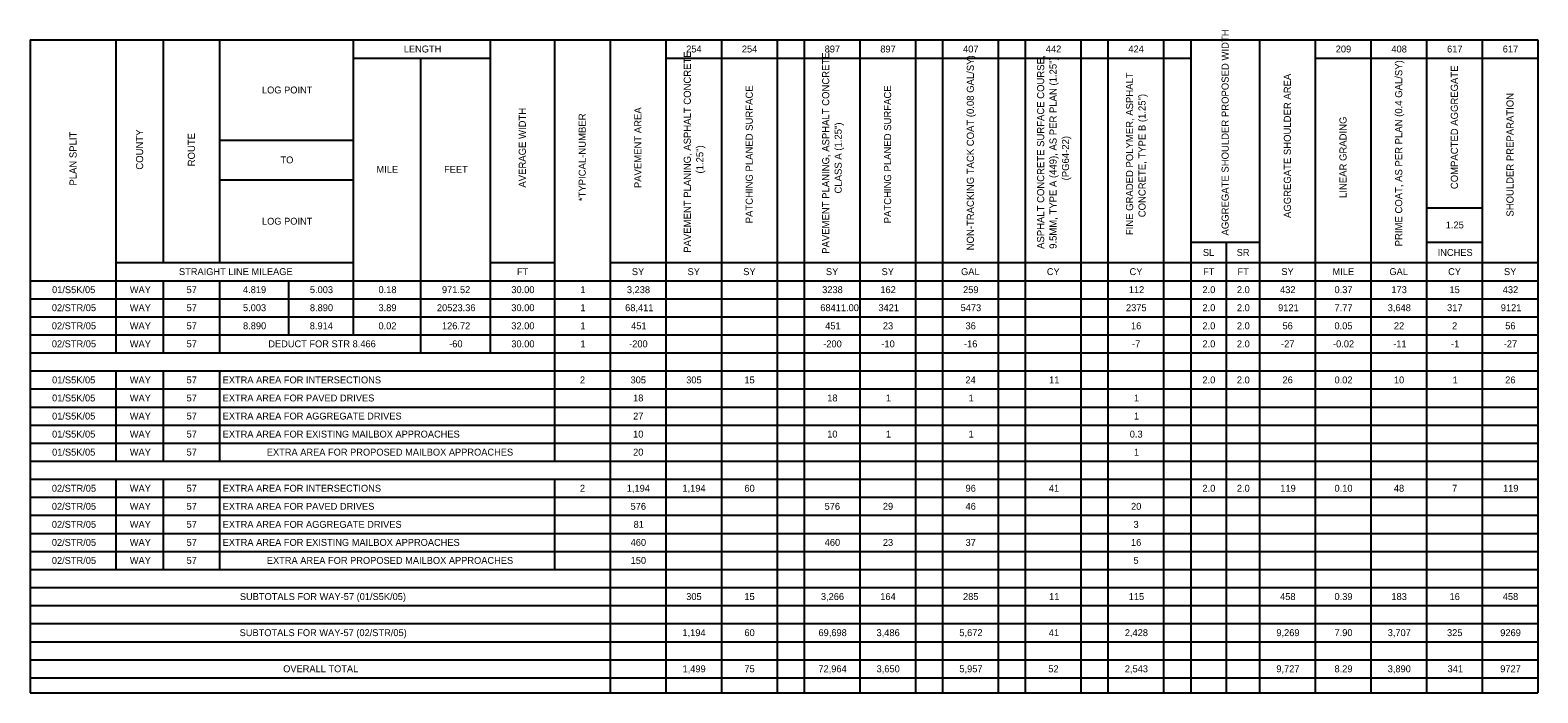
# Model space of a CAD drawing. Extents: x 12069 to 12219, y 28137 to 28231.
# Drawn here: x 12069.45 to 12099.95, y 28161.27 to 28174.68 of the extents above; entities that cross this region are included whole.
import ezdxf

# ---------------------------------------------------------------- set-up
doc = ezdxf.new("R2010")
doc.units = 0
doc.layers.add('SH_Data', color=7, linetype='Continuous')

msp = doc.modelspace()

# ---------------------------------------------------------------- linework, layer by layer
at = {"layer": 'SH_Data'}
for p, q in [((12069.445, 28174.479), (12099.945, 28174.479)), ((12069.445, 28174.479), (12069.445, 28168.149)), ((12071.182, 28174.479), (12071.182, 28168.149)), ((12072.136, 28174.479), (12072.136, 28169.975)), ((12073.277, 28174.479), (12073.277, 28169.975)), ((12075.983, 28174.479), (12075.983, 28168.514)), ((12078.752, 28174.479), (12078.752, 28168.149)), ((12080.05, 28174.479), (12080.05, 28165.957)), ((12081.176, 28174.479), (12081.176, 28161.27)), ((12082.302, 28174.479), (12082.302, 28161.27)), ((12083.428, 28174.479), (12083.428, 28161.27)), ((12084.555, 28174.479), (12084.555, 28161.27)), ((12085.102, 28174.479), (12085.102, 28161.27)), ((12086.228, 28174.479), (12086.228, 28161.27)), ((12087.354, 28174.479), (12087.354, 28161.27)), ((12087.902, 28174.479), (12087.902, 28161.27)), ((12089.028, 28174.479), (12089.028, 28161.27)), ((12089.575, 28174.479), (12089.575, 28161.27)), ((12090.702, 28174.479), (12090.702, 28161.27)), ((12091.249, 28174.479), (12091.249, 28161.27)), ((12092.375, 28174.479), (12092.375, 28161.27)), ((12092.923, 28174.479), (12092.923, 28161.27)), ((12094.315, 28174.479), (12094.315, 28161.27)), ((12095.441, 28174.479), (12095.441, 28161.27)), ((12096.567, 28174.479), (12096.567, 28161.27)), ((12097.693, 28174.479), (12097.693, 28161.27)), ((12098.819, 28174.479), (12098.819, 28161.27)), ((12099.945, 28174.479), (12099.945, 28161.575)), ((12075.983, 28174.114), (12078.752, 28174.114)), ((12077.344, 28174.114), (12077.344, 28168.149)), ((12082.302, 28174.114), (12092.923, 28174.114)), ((12095.441, 28174.114), (12099.945, 28174.114)), ((12073.277, 28172.455), (12075.983, 28172.455)), ((12073.277, 28171.649), (12075.983, 28171.649)), ((12097.693, 28171.086), (12098.819, 28171.086)), ((12092.923, 28170.386), (12094.315, 28170.386)), ((12093.642, 28170.386), (12093.642, 28161.27)), ((12097.693, 28170.386), (12098.819, 28170.386)), ((12071.182, 28169.975), (12075.983, 28169.975)), ((12078.752, 28169.975), (12080.05, 28169.975)), ((12081.176, 28169.975), (12099.945, 28169.975)), ((12069.445, 28169.609), (12099.945, 28169.609)), ((12072.136, 28169.609), (12072.136, 28168.149)), ((12073.277, 28169.609), (12073.277, 28168.149)), ((12074.67, 28169.609), (12074.67, 28168.514)), ((12069.445, 28169.244), (12099.945, 28169.244)), ((12069.445, 28168.879), (12099.945, 28168.879)), ((12069.445, 28168.514), (12099.945, 28168.514)), ((12069.445, 28168.149), (12099.945, 28168.149)), ((12069.445, 28168.149), (12069.445, 28167.783)), ((12069.445, 28167.783), (12099.945, 28167.783)), ((12069.445, 28167.783), (12069.445, 28165.957)), ((12071.182, 28167.783), (12071.182, 28165.957)), ((12072.136, 28167.783), (12072.136, 28165.957)), ((12073.277, 28167.783), (12073.277, 28165.957)), ((12069.445, 28167.418), (12099.945, 28167.418)), ((12069.445, 28167.053), (12099.945, 28167.053)), ((12069.445, 28166.688), (12099.945, 28166.688)), ((12069.445, 28166.323), (12099.945, 28166.323)), ((12069.445, 28165.957), (12099.945, 28165.957)), ((12069.445, 28165.957), (12069.445, 28165.592)), ((12069.445, 28165.592), (12099.945, 28165.592)), ((12069.445, 28165.592), (12069.445, 28161.27)), ((12071.182, 28165.592), (12071.182, 28163.766)), ((12072.136, 28165.592), (12072.136, 28163.766)), ((12073.277, 28165.592), (12073.277, 28163.766)), ((12080.05, 28165.592), (12080.05, 28163.766)), ((12069.445, 28165.227), (12099.945, 28165.227)), ((12069.445, 28164.862), (12099.945, 28164.862)), ((12069.445, 28164.496), (12099.945, 28164.496)), ((12069.445, 28164.131), (12099.945, 28164.131)), ((12069.445, 28163.766), (12099.945, 28163.766)), ((12069.445, 28163.401), (12099.945, 28163.401)), ((12069.445, 28163.036), (12099.945, 28163.036)), ((12069.445, 28162.67), (12099.945, 28162.67)), ((12069.445, 28162.305), (12099.945, 28162.305)), ((12069.445, 28161.94), (12099.945, 28161.94)), ((12069.445, 28161.575), (12099.945, 28161.575)), ((12099.945, 28161.575), (12099.945, 28161.27)), ((12069.445, 28161.27), (12099.945, 28161.27))]:
    msp.add_line(p, q, dxfattribs=at)

# ---------------------------------------------------------------- texts
for s, p in [('AGGREGATE SHOULDER PROPOSED WIDTH', (12093.691, 28170.523)), ('PAVEMENT PLANING, ASPHALT CONCRETE ', (12082.811, 28170.175)), ('PAVEMENT PLANING, ASPHALT CONCRETE, ', (12085.611, 28170.153)), ('NON-TRACKING TACK COAT (0.08 GAL/SY)', (12088.537, 28170.223)), ('ASPHALT CONCRETE SURFACE COURSE, ', (12089.959, 28170.252)), ('9.5MM, TYPE A (449), AS PER PLAN (1.25") ', (12090.21, 28170.253)), ('FINE GRADED POLYMER, ASPHALT ', (12091.758, 28170.53)), ('AGGREGATE SHOULDER AREA', (12094.95, 28170.877)), ('PRIME COAT, AS PER PLAN (0.4 GAL/SY)', (12097.202, 28170.304)), ('COMPACTED AGGREGATE', (12098.328, 28171.461)), ('PATCHING PLANED SURFACE', (12084.064, 28170.77)), ('PATCHING PLANED SURFACE', (12086.863, 28170.77)), ('CONCRETE, TYPE B (1.25")', (12092.01, 28170.892)), ('SHOULDER PREPARATION', (12099.454, 28170.905)), ('AVERAGE WIDTH', (12079.473, 28171.492)), ('*TYPICAL-NUMBER', (12080.685, 28171.218)), ('PAVEMENT AREA', (12081.811, 28171.481)), ('LINEAR GRADING', (12096.076, 28171.282)), ('PLAN SPLIT', (12070.385, 28171.533)), ('COUNTY', (12071.731, 28171.855)), ('ROUTE', (12072.779, 28171.923)), ('CLASS A (1.25")', (12085.863, 28171.373)), ('(1.25")', (12083.063, 28171.777)), ('(PG64-22)', (12090.462, 28171.638))]:
    msp.add_text(s, height=0.1439, rotation=90, dxfattribs=at).set_placement(p)
for s, p in [('LENGTH', (12077.003, 28174.226)), ('254', (12082.717, 28174.226)), ('254', (12083.843, 28174.226)), ('897', (12085.518, 28174.226)), ('897', (12086.644, 28174.226)), ('407', (12088.318, 28174.226)), ('442', (12089.992, 28174.226)), ('424', (12091.663, 28174.226)), ('209', (12095.857, 28174.226)), ('408', (12096.983, 28174.226)), ('617', (12098.109, 28174.226)), ('617', (12099.235, 28174.226)), ('LOG POINT', (12074.135, 28173.397)), ('TO', (12074.51, 28171.982)), ('MILE', (12076.452, 28171.792)), ('FEET', (12077.819, 28171.792)), ('LOG POINT', (12074.135, 28170.742)), ('1.25', (12098.083, 28170.666)), ('SL', (12093.169, 28170.11)), ('SR', (12093.853, 28170.11)), ('INCHES', (12097.919, 28170.11)), ('STRAIGHT LINE MILEAGE', (12072.456, 28169.722)), ('FT', (12079.292, 28169.722)), ('SY', (12081.618, 28169.722)), ('SY', (12082.745, 28169.722)), ('SY', (12083.871, 28169.722)), ('SY', (12085.544, 28169.722)), ('SY', (12086.67, 28169.722)), ('GAL', (12088.277, 28169.722)), ('CY', (12090.013, 28169.722)), ('CY', (12091.686, 28169.722)), ('FT', (12093.174, 28169.722)), ('FT', (12093.87, 28169.722)), ('SY', (12094.757, 28169.722)), ('MILE', (12095.792, 28169.722)), ('GAL', (12096.942, 28169.722)), ('CY', (12098.13, 28169.722)), ('SY', (12099.261, 28169.722)), ('01/S5K/05', (12069.889, 28169.357)), ('WAY', (12071.461, 28169.357)), ('57', (12072.61, 28169.357)), ('4.819', (12073.751, 28169.357)), ('5.003', (12075.104, 28169.357)), ('0.18', (12076.492, 28169.357)), ('971.52', (12077.776, 28169.357)), ('30.00', (12079.179, 28169.357)), ('1', (12080.577, 28169.357)), ('3,238', (12081.517, 28169.357)), ('3238', (12085.468, 28169.357)), ('162', (12086.645, 28169.357)), ('259', (12088.318, 28169.357)), ('112', (12091.671, 28169.357)), ('2.0', (12093.161, 28169.357)), ('2.0', (12093.857, 28169.357)), ('432', (12094.731, 28169.357)), ('0.37', (12095.832, 28169.357)), ('173', (12096.983, 28169.357)), ('15', (12098.158, 28169.357)), ('432', (12099.236, 28169.357)), ('02/STR/05', (12069.884, 28168.992)), ('WAY', (12071.461, 28168.992)), ('57', (12072.61, 28168.992)), ('5.003', (12073.751, 28168.992)), ('8.890', (12075.105, 28168.992)), ('3.89', (12076.492, 28168.992)), ('20523.36', (12077.674, 28168.992)), ('30.00', (12079.179, 28168.992)), ('1', (12080.577, 28168.992)), ('68,411', (12081.482, 28168.992)), ('68411.00', (12085.43, 28168.992)), ('3421', (12086.605, 28168.992)), ('5473', (12088.268, 28168.992)), ('2375', (12091.614, 28168.992)), ('2.0', (12093.161, 28168.992)), ('2.0', (12093.857, 28168.992)), ('9121', (12094.691, 28168.992)), ('7.77', (12095.832, 28168.992)), ('3,648', (12096.908, 28168.992)), ('317', (12098.109, 28168.992)), ('9121', (12099.196, 28168.992)), ('02/STR/05', (12069.884, 28168.626)), ('WAY', (12071.461, 28168.626)), ('57', (12072.61, 28168.626)), ('8.890', (12073.752, 28168.626)), ('8.914', (12075.102, 28168.626)), ('0.02', (12076.492, 28168.626)), ('126.72', (12077.776, 28168.626)), ('32.00', (12079.179, 28168.626)), ('1', (12080.577, 28168.626)), ('451', (12081.603, 28168.626)), ('451', (12085.529, 28168.626)), ('23', (12086.695, 28168.626)), ('36', (12088.368, 28168.626)), ('16', (12091.715, 28168.626)), ('2.0', (12093.161, 28168.626)), ('2.0', (12093.857, 28168.626)), ('56', (12094.78, 28168.626)), ('0.05', (12095.831, 28168.626)), ('22', (12097.034, 28168.626)), ('2', (12098.21, 28168.626)), ('56', (12099.285, 28168.626)), ('02/STR/05', (12069.884, 28168.261)), ('WAY', (12071.461, 28168.261)), ('57', (12072.61, 28168.261)), ('DEDUCT FOR STR 8.466', (12074.263, 28168.261)), ('-60', (12077.922, 28168.261)), ('30.00', (12079.179, 28168.261)), ('1', (12080.577, 28168.261)), ('-200', (12081.563, 28168.261)), ('-200', (12085.489, 28168.261)), ('-10', (12086.665, 28168.261)), ('-16', (12088.337, 28168.261)), ('-7', (12091.736, 28168.261)), ('2.0', (12093.161, 28168.261)), ('2.0', (12093.857, 28168.261)), ('-27', (12094.751, 28168.261)), ('-0.02', (12095.802, 28168.261)), ('-11', (12097.019, 28168.261)), ('-1', (12098.19, 28168.261)), ('-27', (12099.256, 28168.261)), ('01/S5K/05', (12069.889, 28167.531)), ('WAY', (12071.461, 28167.531)), ('57', (12072.61, 28167.531)), ('EXTRA AREA FOR INTERSECTIONS', (12073.34, 28167.531)), ('2', (12080.567, 28167.531)), ('305', (12081.591, 28167.531)), ('305', (12082.717, 28167.531)), ('15', (12083.894, 28167.531)), ('24', (12088.366, 28167.531)), ('11', (12090.058, 28167.531)), ('2.0', (12093.161, 28167.531)), ('2.0', (12093.857, 28167.531)), ('26', (12094.78, 28167.531)), ('0.02', (12095.832, 28167.531)), ('10', (12097.034, 28167.531)), ('1', (12098.221, 28167.531)), ('26', (12099.285, 28167.531)), ('01/S5K/05', (12069.889, 28167.166)), ('WAY', (12071.461, 28167.166)), ('57', (12072.61, 28167.166)), ('EXTRA AREA FOR PAVED DRIVES', (12073.34, 28167.166)), ('18', (12081.643, 28167.166)), ('18', (12085.569, 28167.166)), ('1', (12086.756, 28167.166)), ('1', (12088.429, 28167.166)), ('1', (12091.776, 28167.166)), ('01/S5K/05', (12069.889, 28166.8)), ('WAY', (12071.461, 28166.8)), ('57', (12072.61, 28166.8)), ('EXTRA AREA FOR AGGREGATE DRIVES', (12073.34, 28166.8)), ('27', (12081.643, 28166.8)), ('1', (12091.776, 28166.8)), ('01/S5K/05', (12069.889, 28166.435)), ('WAY', (12071.461, 28166.435)), ('57', (12072.61, 28166.435)), ('EXTRA AREA FOR EXISTING MAILBOX APPROACHES', (12073.34, 28166.435)), ('10', (12081.643, 28166.435)), ('10', (12085.569, 28166.435)), ('1', (12086.756, 28166.435)), ('1', (12088.429, 28166.435)), ('0.3', (12091.69, 28166.435)), ('01/S5K/05', (12069.889, 28166.07)), ('WAY', (12071.461, 28166.07)), ('57', (12072.61, 28166.07)), ('EXTRA AREA FOR PROPOSED MAILBOX APPROACHES', (12074.233, 28166.07)), ('20', (12081.643, 28166.07)), ('1', (12091.776, 28166.07)), ('02/STR/05', (12069.884, 28165.339)), ('WAY', (12071.461, 28165.339)), ('57', (12072.61, 28165.339)), ('EXTRA AREA FOR INTERSECTIONS', (12073.34, 28165.339)), ('2', (12080.567, 28165.339)), ('1,194', (12081.515, 28165.339)), ('1,194', (12082.641, 28165.339)), ('60', (12083.895, 28165.339)), ('96', (12088.368, 28165.339)), ('41', (12090.053, 28165.339)), ('2.0', (12093.161, 28165.339)), ('2.0', (12093.857, 28165.339)), ('119', (12094.736, 28165.339)), ('0.10', (12095.832, 28165.339)), ('48', (12097.033, 28165.339)), ('7', (12098.21, 28165.339)), ('119', (12099.241, 28165.339)), ('02/STR/05', (12069.884, 28164.974)), ('WAY', (12071.461, 28164.974)), ('57', (12072.61, 28164.974)), ('EXTRA AREA FOR PAVED DRIVES', (12073.34, 28164.974)), ('576', (12081.592, 28164.974)), ('576', (12085.517, 28164.974)), ('29', (12086.695, 28164.974)), ('46', (12088.368, 28164.974)), ('20', (12091.716, 28164.974)), ('02/STR/05', (12069.884, 28164.609)), ('WAY', (12071.461, 28164.609)), ('57', (12072.61, 28164.609)), ('EXTRA AREA FOR AGGREGATE DRIVES', (12073.34, 28164.609)), ('81', (12081.653, 28164.609)), ('3', (12091.766, 28164.609)), ('02/STR/05', (12069.884, 28164.244)), ('WAY', (12071.461, 28164.244)), ('57', (12072.61, 28164.244)), ('EXTRA AREA FOR EXISTING MAILBOX APPROACHES', (12073.34, 28164.244)), ('460', (12081.593, 28164.244)), ('460', (12085.519, 28164.244)), ('23', (12086.695, 28164.244)), ('37', (12088.368, 28164.244)), ('16', (12091.715, 28164.244)), ('02/STR/05', (12069.884, 28163.879)), ('WAY', (12071.461, 28163.879)), ('57', (12072.61, 28163.879)), ('EXTRA AREA FOR PROPOSED MAILBOX APPROACHES', (12074.233, 28163.879)), ('150', (12081.593, 28163.879)), ('5', (12091.765, 28163.879)), ('SUBTOTALS FOR WAY-57 (01/S5K/05)', (12073.688, 28163.148)), ('305', (12082.717, 28163.148)), ('15', (12083.894, 28163.148)), ('3,266', (12085.442, 28163.148)), ('164', (12086.643, 28163.148)), ('285', (12088.317, 28163.148)), ('11', (12090.058, 28163.148)), ('115', (12091.669, 28163.148)), ('458', (12094.731, 28163.148)), ('0.39', (12095.832, 28163.148)), ('183', (12096.983, 28163.148)), ('16', (12098.159, 28163.148)), ('458', (12099.236, 28163.148)), ('SUBTOTALS FOR WAY-57 (02/STR/05)', (12073.683, 28162.418)), ('1,194', (12082.641, 28162.418)), ('60', (12083.895, 28162.418)), ('69,698', (12085.393, 28162.418)), ('3,486', (12086.568, 28162.418)), ('5,672', (12088.243, 28162.418)), ('41', (12090.053, 28162.418)), ('2,428', (12091.59, 28162.418)), ('9,269', (12094.656, 28162.418)), ('7.90', (12095.832, 28162.418)), ('3,707', (12096.908, 28162.418)), ('325', (12098.108, 28162.418)), ('9269', (12099.185, 28162.418)), ('OVERALL TOTAL', (12074.564, 28161.687)), ('1,499', (12082.643, 28161.687)), ('75', (12083.894, 28161.687)), ('72,964', (12085.391, 28161.687)), ('3,650', (12086.569, 28161.687)), ('5,957', (12088.243, 28161.687)), ('52', (12090.042, 28161.687)), ('2,543', (12091.59, 28161.687)), ('9,727', (12094.655, 28161.687)), ('8.29', (12095.832, 28161.687)), ('3,890', (12096.908, 28161.687)), ('341', (12098.12, 28161.687)), ('9727', (12099.185, 28161.687))]:
    msp.add_text(s, height=0.14, dxfattribs=at).set_placement(p)

doc.saveas('drawing.dxf')
